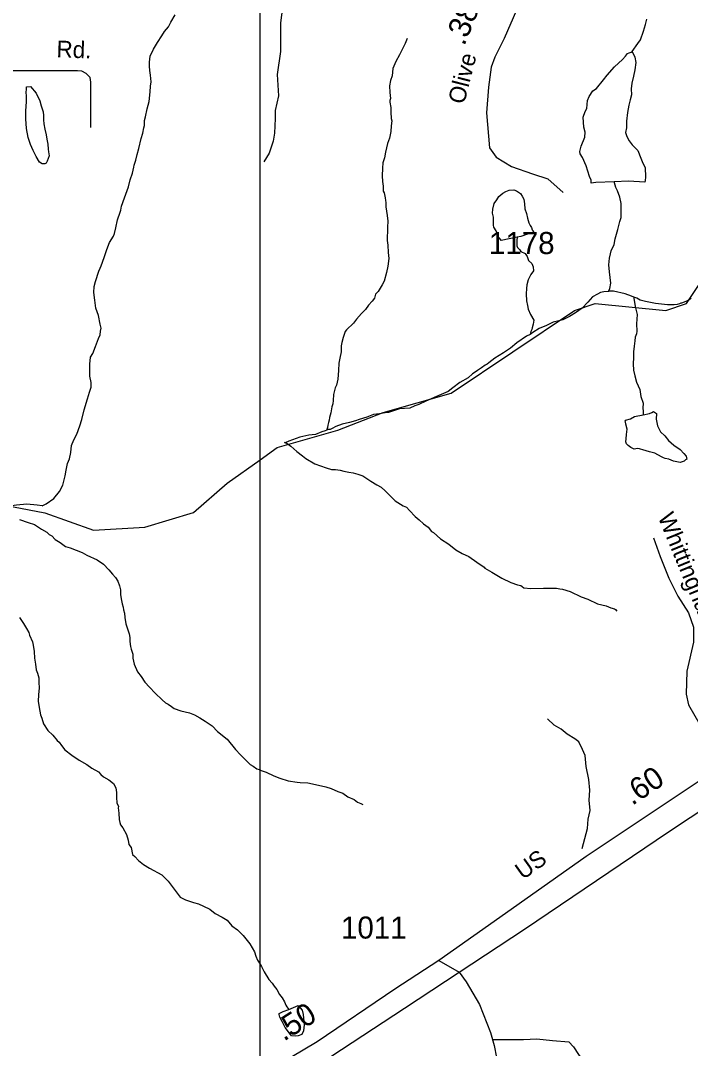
# Model space of a CAD drawing. Extents: x 2001466 to 2224147, y 644118 to 847247.
# Drawn here: x 2019117 to 2022908, y 703581 to 709402 of the extents above; entities that cross this region are included whole.
import ezdxf

# ---------------------------------------------------------------- set-up
doc = ezdxf.new("R2010")
doc.units = 0
for name, color, linetype in [('Exist Hydrographic Creek Single Shore', 7, 'Continuous'), ('Exist Hydrographic Misc Water Feature', 7, 'Continuous'), ('Exist Railroad Mainline', 7, 'Continuous'), ('Exist Road Non-System Type 51', 7, 'Continuous'), ('Exist Road Non-System Type 51 Label', 7, 'Continuous'), ('Exist Road Secondary Mileage Hundredths English Label', 7, 'Continuous'), ('Exist Road Secondary Type 41 Attributed', 7, 'Continuous'), ('Exist Road Secondary Type 51 Attributed', 7, 'Continuous'), ('Exist Road Secondary Type 51 Label', 7, 'Continuous'), ('Exist Road Secondary Type 51 Number Label', 7, 'Continuous'), ('Map Preparation Inset Cut Line', 7, 'Continuous')]:
    doc.layers.add(name, color=color, linetype=linetype)

msp = doc.modelspace()

# ---------------------------------------------------------------- linework, layer by layer
at = {"layer": 'Exist Hydrographic Creek Single Shore'}
for points in [[(2020472.9, 706915.1), (2020569.7, 706983.8), (2020911.7, 707081.9)], [(2015804.7, 705555.1), (2015821.7, 705613.9), (2015996.8, 705820.2), (2016171.7, 705895.4), (2016662.8, 706013.4), (2017037.7, 705972.9), (2017254.8, 705998.1), (2018020.7, 706222), (2018162.8, 706363.5), (2018770.8, 706630), (2018986.7, 706665), (2019253.7, 706613.6), (2019528.9, 706516.1), (2019820.8, 706533.1), (2020095.8, 706616.1), (2020286.7, 706782.9), (2020472.9, 706915.1)]]:
    msp.add_lwpolyline(points, dxfattribs=at)
at = {"layer": 'Exist Hydrographic Misc Water Feature'}
for points in [[(2019239.3, 706653.2), (2019261.3, 706665.2), (2019305.1, 706695.2), (2019337.1, 706735.3), (2019355.2, 706771.3), (2019369.1, 706823.2), (2019375.1, 706855.2), (2019383.1, 706893.3), (2019393.1, 706919.3), (2019401.1, 706955.2), (2019405, 706995.2), (2019418.9, 707027.3), (2019434.9, 707059.3), (2019453, 707107.2), (2019462.8, 707143.3), (2019477, 707197.3), (2019494.8, 707259.2), (2019506.7, 707297.3), (2019516.8, 707325.3), (2019516.8, 707351.3), (2019508.8, 707387.2), (2019508.8, 707417.3), (2019508.8, 707455.3), (2019512.7, 707495.3), (2019524.8, 707517.2), (2019540.7, 707555.3), (2019558.6, 707601.3), (2019566.6, 707621.3), (2019568.6, 707643.2), (2019572.7, 707659.2), (2019566.6, 707683.3), (2019558.6, 707731.3), (2019542.6, 707773.2), (2019536.6, 707819.2), (2019530.5, 707861.2), (2019532.3, 707895.2), (2019540.3, 707923.2), (2019560.4, 707983.2), (2019566.4, 707999.3), (2019572.5, 708013.2), (2019590.4, 708059.2), (2019604.3, 708105.2), (2019620.3, 708145.2), (2019642.2, 708181.3), (2019648.4, 708195.2), (2019656.4, 708227.2), (2019664.4, 708273.3), (2019680.2, 708317.3), (2019684.3, 708327.3), (2019688.2, 708351.2), (2019704.2, 708397.3), (2019728.2, 708459.3), (2019736.2, 708499.3), (2019750.1, 708537.3), (2019758.1, 708571.3), (2019760.2, 708583.3), (2019770, 708611.2), (2019776.1, 708643.3), (2019786, 708677.3), (2019799.9, 708733.3), (2019807.9, 708763.2), (2019813.9, 708793.3), (2019818, 708807.3), (2019818, 708835.3), (2019823.9, 708857.3), (2019833.8, 708901.2), (2019843.8, 708943.3), (2019849.8, 708997.3), (2019851.8, 709029.2), (2019855.9, 709055.3), (2019851.8, 709093.3), (2019847.7, 709119.3), (2019845.7, 709143.3), (2019845.7, 709165.2), (2019849.8, 709199.2), (2019869.6, 709239.3), (2019891.8, 709277.3), (2019915.6, 709315.3), (2019931.6, 709339.3), (2019953.5, 709365.3), (2019967.7, 709393.3), (2019991.7, 709433.4)], [(2022578.7, 709226.7), (2022611.4, 709271), (2022625.3, 709292.9), (2022643.2, 709340.9), (2022653.2, 709379), (2022661.2, 709409)], [(2021305.4, 709300.1), (2021293.5, 709272.1), (2021261.5, 709208.1), (2021241.7, 709170.1), (2021223.6, 709130.1), (2021219.5, 709088.1), (2021209.7, 709062.1), (2021205.6, 709032.1), (2021207.6, 708994.1), (2021209.7, 708960.1), (2021207.6, 708948.1), (2021207.6, 708940.1), (2021211.7, 708910.1), (2021211.7, 708882.1), (2021213.8, 708846.1), (2021217.7, 708834.2), (2021213.8, 708806.1), (2021211.7, 708774.1), (2021205.8, 708736.2), (2021193.9, 708706.2), (2021181.8, 708656.1), (2021175.8, 708624.1), (2021167.8, 708596.1), (2021166, 708566.1), (2021163.9, 708522.1), (2021166, 708490.2), (2021169.9, 708464.2), (2021169.9, 708436.2), (2021174, 708426.2), (2021175.8, 708416.1), (2021179.9, 708398.1), (2021182, 708382.2), (2021184, 708372.2), (2021184, 708362.2), (2021184, 708346.2), (2021192, 708298.2), (2021196.1, 708266.2), (2021194.1, 708232.2), (2021194.1, 708206.2), (2021192, 708176.2), (2021192.2, 708156.2), (2021196.1, 708130.1), (2021198.2, 708088.2), (2021202.1, 708054.2), (2021196.1, 708010.2), (2021188.1, 707974.2), (2021174.2, 707926.2), (2021164.3, 707904.2), (2021140.4, 707868.1), (2021126.2, 707852.2), (2021120.3, 707830.2), (2021106.3, 707812.2), (2021086.2, 707790.2), (2021068.4, 707766.2), (2021046.4, 707742.2), (2021018.3, 707710.1), (2021000.5, 707688.2), (2020962.4, 707650.1), (2020954.4, 707640.2), (2020942.5, 707606.1), (2020934.5, 707578.1), (2020930.6, 707560.1), (2020930.6, 707526.1), (2020924.4, 707490.1), (2020918.5, 707462.1), (2020916.4, 707420.1), (2020912.7, 707370.2), (2020904.8, 707336.2), (2020896.5, 707322.1), (2020888.6, 707284.2), (2020886.7, 707250.2), (2020884.7, 707232.2), (2020878.7, 707214.1), (2020872.6, 707180.1), (2020864.8, 707154.1), (2020862.7, 707138.1), (2020858.8, 707126.2), (2020856.8, 707110.1), (2020854.7, 707098.1), (2020850.8, 707086.2), (2020850.8, 707082.2)], [(2022475.9, 708488.9), (2022373.7, 708484.9), (2022345.9, 708480.9), (2022345.9, 708496.9), (2022337.9, 708518.9), (2022317.8, 708578.9), (2022297.7, 708626.8), (2022283.7, 708646.8), (2022281.7, 708660.8), (2022289.7, 708690.8), (2022309.8, 708740.8), (2022311.6, 708768.8), (2022305.5, 708798.8), (2022301.6, 708854.8), (2022311.6, 708886.8), (2022321.7, 708902.7), (2022325.6, 708948.8), (2022335.6, 708970.8), (2022355.5, 709002.8), (2022377.4, 709016.8), (2022415.4, 709066.8), (2022437.5, 709092.9), (2022479.3, 709138.9), (2022501.3, 709160.9), (2022523.2, 709180.9), (2022541.3, 709200.9), (2022551.3, 709214.9), (2022561.4, 709218.9), (2022573.3, 709222.9), (2022578.7, 709226.7)], [(2022578.7, 709226.7), (2022593.4, 709194.9), (2022599.3, 709164.9), (2022593.4, 709123), (2022585.4, 709086.9), (2022577.4, 709046.9), (2022573.5, 709014.9), (2022575.5, 708981), (2022567.5, 708952.9), (2022559.5, 708922.9), (2022551.5, 708880.9), (2022545.6, 708831), (2022545.6, 708794.9), (2022541.5, 708766.9), (2022547.6, 708744.9), (2022561.8, 708721), (2022577.8, 708697), (2022609.8, 708665), (2022627.6, 708623), (2022639.7, 708595), (2022651.6, 708569), (2022653.6, 708515.1), (2022651.6, 708495), (2022649.7, 708487.1), (2022557.9, 708493), (2022475.9, 708488.9)], [(2019253.9, 708786.9), (2019262.1, 708754.9), (2019266.2, 708730.9), (2019270.1, 708701), (2019272.1, 708673), (2019274.2, 708659), (2019278.1, 708635), (2019268, 708604.9), (2019262.1, 708595), (2019254.3, 708590.9), (2019238.1, 708590.9), (2019224.1, 708598.9), (2019204, 708630.9), (2019188.1, 708664.9), (2019172.1, 708698.9), (2019160.2, 708738.9), (2019150.1, 708790.9), (2019146, 708844.9), (2019146, 708890.9), (2019149.9, 708940.9), (2019149.9, 708970.9), (2019147.9, 708998.8), (2019149.9, 709008.8), (2019149.9, 709026.8), (2019172.1, 709028.8), (2019204, 708990.9), (2019226, 708946.9), (2019234, 708918.9), (2019244, 708884.9), (2019245.9, 708864.9), (2019245.9, 708839), (2019247.9, 708817), (2019253.9, 708786.9)], [(2022444.1, 707867), (2022452.1, 707885), (2022458, 707915), (2022450, 707979), (2022446.1, 708019), (2022450, 708057), (2022456, 708081), (2022459.9, 708097), (2022475.9, 708133), (2022482, 708165), (2022498, 708219), (2022507.8, 708263), (2022515.8, 708287), (2022515.8, 708319), (2022515.8, 708365), (2022507.8, 708401), (2022495.7, 708437), (2022485.7, 708456.9), (2022477.7, 708482.9), (2022475.9, 708488.9)], [(2021928, 708174.6), (2021837.9, 708156.6), (2021829.9, 708166.6), (2021820.1, 708176.5), (2021818.1, 708190.5), (2021808, 708210.5), (2021796.1, 708232.6), (2021794.1, 708242.6), (2021793.9, 708270.6), (2021793.9, 708288.5), (2021787.9, 708310.5), (2021790, 708334.5), (2021798, 708366.6), (2021811.9, 708386.6), (2021824, 708404.6), (2021845.9, 708424.5), (2021864, 708434.5), (2021881.8, 708440.6), (2021907.9, 708442.6), (2021923.9, 708436.6), (2021946, 708422.6), (2021955.8, 708406.6), (2021965.9, 708390.7), (2021970, 708364.7), (2021971.8, 708334.7), (2021979.8, 708308.7), (2021986, 708282.7), (2021994, 708256.7), (2022002, 708240.7), (2022007.9, 708230.7), (2022012, 708216.7), (2022022.1, 708206.7), (2022018, 708202.7), (2021948.1, 708178.7), (2021928, 708174.6)], [(2021928, 708174.6), (2021926.1, 708158.6), (2021926.1, 708126.7), (2021930, 708116.7), (2021942.1, 708102.7), (2021948.1, 708094.7), (2021972, 708082.7), (2021983.9, 708064.7), (2021991.9, 708042.7), (2022010, 708026.7), (2022018.2, 708006.8), (2022020.2, 707984.8), (2022004.2, 707962.7), (2021990.1, 707932.7), (2021982.1, 707904.7), (2021980.2, 707884.7), (2021978.2, 707854.8), (2021980.2, 707814.7), (2021986.2, 707788.7), (2021990.3, 707766.7), (2022002.2, 707736.8), (2022022.3, 707704.8), (2022018.2, 707682.8), (2022012.2, 707660.7), (2022010.2, 707652.7), (2022004.2, 707640.7), (2022002.2, 707632.7), (2022000.3, 707624.7)], [(2020911.7, 707081.9), (2021169.7, 707181.6), (2021553.7, 707291.9), (2022252.8, 707760), (2022369.8, 707800.3), (2022769.7, 707759.3), (2022885.8, 707799.5), (2023002.8, 707974.4)], [(2022444.1, 707867), (2022418.2, 707865), (2022400.2, 707861), (2022382.2, 707853), (2022354.1, 707836.9), (2022328.2, 707806.9), (2022296.2, 707772.9), (2022258.1, 707746.9), (2022224.1, 707724.9), (2022202.1, 707714.9), (2022186.3, 707706.9), (2022164.2, 707700.9), (2022132.2, 707692.8), (2022094.3, 707674.8), (2022052.2, 707658.8), (2022016.3, 707634.8), (2022000.3, 707624.7)], [(2022588.2, 707835.1), (2022574.1, 707841.1), (2022538.2, 707855.1), (2022472.2, 707869), (2022452.1, 707869), (2022444.1, 707867)], [(2022588.2, 707835.1), (2022588.2, 707829.1), (2022596.2, 707783), (2022606.1, 707737.1), (2022602.2, 707685.1), (2022604.2, 707643.1), (2022602.2, 707627.1), (2022596.2, 707609.1), (2022594.2, 707587.1), (2022590.3, 707557.1), (2022586.2, 707525.1), (2022586.2, 707493.2), (2022584.3, 707457.1), (2022586.4, 707421.1), (2022594.4, 707389.2), (2022602.4, 707353.2), (2022622.5, 707313.2), (2022628.4, 707273.2), (2022640.5, 707235.2), (2022638.5, 707207.2), (2022640.5, 707189.2), (2022640.5, 707177.2), (2022640.5, 707169.2)], [(2022912, 707827.2), (2022892.1, 707815.2), (2022858.1, 707801.2), (2022854, 707801.2), (2022846.2, 707797.2), (2022834.1, 707793.2), (2022816, 707791.2), (2022798.2, 707791.2), (2022778.1, 707791.2), (2022744.1, 707795.2), (2022710.2, 707799.2), (2022654.1, 707811.1), (2022624.1, 707819.1), (2022604.2, 707829.1), (2022588.2, 707835.1)], [(2022000.3, 707624.7), (2021980.2, 707614.7), (2021926.3, 707576.8), (2021890.4, 707546.7), (2021850.5, 707520.7), (2021800.4, 707490.6), (2021766.4, 707462.6), (2021758.4, 707456.6), (2021746.5, 707450.6), (2021726.4, 707434.6), (2021702.6, 707420.6), (2021690.3, 707410.6), (2021674.5, 707400.6), (2021650.5, 707378.6), (2021602.5, 707352.5), (2021562.6, 707322.5), (2021536.5, 707300.6), (2021470.5, 707272.5), (2021410.6, 707246.5), (2021370.6, 707228.4), (2021348.7, 707220.4), (2021320.6, 707206.4), (2021290.7, 707204.3), (2021260.7, 707202.3), (2021210.7, 707186.3), (2021198.6, 707182.3), (2021192.6, 707182.3), (2021168.7, 707178.3), (2021148.6, 707174.3), (2021114.7, 707170.3), (2021076.6, 707156.3), (2021032.7, 707142.2), (2021012.8, 707134.2), (2020978.8, 707126.2), (2020936.7, 707116.2), (2020900.9, 707102.2), (2020880.8, 707092.2), (2020868.9, 707086.1), (2020856.8, 707086.2), (2020850.8, 707082.2)], [(2022640.5, 707169.2), (2022676.6, 707177.3), (2022690.5, 707181.3), (2022698.5, 707187.3), (2022716.6, 707177.3), (2022714.5, 707145.2), (2022722.5, 707107.2), (2022738.5, 707073.3), (2022762.5, 707049.3), (2022784.5, 707023.3), (2022814.4, 706997.3), (2022850.5, 706973.4), (2022870.6, 706949.4), (2022884.5, 706935.4), (2022886.6, 706925.4), (2022888.6, 706917.4), (2022880.6, 706913.4), (2022872.6, 706907.4), (2022850.7, 706899.4), (2022812.6, 706907.4), (2022786.7, 706917.3), (2022764.6, 706921.3), (2022756.6, 706925.3), (2022744.7, 706931.3), (2022706.5, 706951.3), (2022676.6, 706959.2), (2022638.7, 706971.2), (2022626.6, 706975.2), (2022620.6, 706977.2), (2022608.5, 706979.2), (2022590.7, 706975.2), (2022582.7, 706979.2), (2022570.6, 706983.2), (2022556.7, 706995.2), (2022546.6, 707005.2), (2022542.7, 707015.2), (2022544.6, 707033.2), (2022546.6, 707057.2), (2022548.4, 707073.2), (2022550.5, 707087.2), (2022542.5, 707115.2), (2022540.5, 707129.1), (2022538.6, 707133.2), (2022540.5, 707139.2), (2022568.5, 707147.2), (2022592.5, 707159.2), (2022640.5, 707169.2)], [(2020850.8, 707082.2), (2020840.8, 707078.2), (2020822.7, 707072.1), (2020786.8, 707058.1), (2020748.7, 707054.1), (2020696.8, 707042), (2020656.8, 707028), (2020634.9, 707020), (2020617.8, 707012.7), (2020614.2, 707011.2), (2020610.9, 707011.9)], [(2020610.9, 707011.9), (2020614.2, 707011.2), (2020617.8, 707012.7), (2020646.8, 706992), (2020680.8, 706962), (2020712.8, 706936.1), (2020730.9, 706922.1), (2020782.9, 706892.1), (2020846.9, 706868.2), (2020876.9, 706860.2), (2020898.8, 706860.2), (2020924.8, 706856.2), (2020946.8, 706850.2), (2020974.9, 706844.2), (2020998.9, 706840.2), (2021024.9, 706832.3), (2021054.8, 706824.3), (2021098.9, 706794.3), (2021133, 706772.3), (2021157, 706760.3), (2021181, 706738.4), (2021236.9, 706682.4), (2021282.9, 706654.5), (2021300.9, 706646.5), (2021319, 706626.5), (2021350.9, 706592.5), (2021373.1, 706574.5), (2021397.1, 706552.5), (2021422.9, 706532.5), (2021443, 706508.5), (2021454.9, 706502.6), (2021493, 706466.6), (2021541, 706436.6), (2021581, 706404.7), (2021616.9, 706384.7), (2021653.2, 706366.7), (2021699.1, 706334.7), (2021741.2, 706306.8), (2021745.1, 706300.7), (2021785, 706278.8), (2021841, 706244.8), (2021891.1, 706218.9), (2021929.2, 706206.9), (2021949.1, 706202.9), (2021955, 706196.9), (2021965.1, 706188.9), (2022005.1, 706185), (2022077, 706187), (2022115.2, 706187), (2022151.1, 706187.1), (2022169.1, 706183.1), (2022185.1, 706181.1), (2022227.1, 706169.1), (2022289.1, 706139.1), (2022327.2, 706125.2), (2022383.2, 706099.2), (2022431.2, 706087.3), (2022457.2, 706075.3), (2022479.1, 706071.3), (2022485.1, 706067.3), (2022491, 706057.2)], [(2019239.3, 706653.2), (2019211.2, 706657.2), (2019151.4, 706663.1), (2019093.3, 706657.1), (2019055.2, 706651.1), (2019039.2, 706651.1)], [(2019111.4, 706577.1), (2019159.3, 706559.1), (2019195.2, 706547.2), (2019235.2, 706521.2), (2019265.4, 706505.3), (2019279.3, 706491.3), (2019293.2, 706483.3), (2019313.3, 706463.3), (2019341.4, 706445.3), (2019371.4, 706423.3), (2019397.4, 706415.3), (2019431.5, 706403.3), (2019465.3, 706389.4), (2019491.3, 706373.4), (2019549.4, 706347.4), (2019585.4, 706323.4), (2019615.4, 706291.4), (2019637.3, 706267.5), (2019653.3, 706247.5), (2019667.5, 706227.5), (2019677.3, 706201.5), (2019681.4, 706177.5), (2019681.4, 706149.5), (2019687.6, 706117.6), (2019691.5, 706099.6), (2019697.4, 706079.6), (2019699.5, 706065.6), (2019705.4, 706045.6), (2019707.5, 706021.6), (2019713.4, 705985.6), (2019721.6, 705957.6), (2019731.6, 705929.6), (2019735.5, 705907.6), (2019735.5, 705885.6), (2019739.6, 705857.7), (2019743.5, 705841.6), (2019751.5, 705813.6), (2019751.5, 705791.6), (2019759.5, 705757.6), (2019777.8, 705713.7), (2019799.7, 705687.7), (2019819.8, 705655.6), (2019845.7, 705627.7), (2019877.6, 705593.7), (2019917.6, 705555.8), (2019937.7, 705537.8), (2019951.7, 705529.8), (2019971.8, 705517.8), (2019985.7, 705505.8), (2020023.8, 705493.8), (2020073.7, 705481.8), (2020101.8, 705469.9), (2020131.7, 705453.9), (2020161.8, 705433.9), (2020201.8, 705408), (2020231.8, 705375.9), (2020285.9, 705332), (2020333.9, 705274), (2020361.8, 705244.1), (2020391.9, 705214.1), (2020415.9, 705188.1), (2020433.7, 705180.1), (2020454, 705164.2), (2020468, 705160.2), (2020478, 705154.1), (2020505.9, 705146.1), (2020550, 705124.2), (2020584, 705112.2), (2020632, 705096.2), (2020681.9, 705088.3), (2020699.9, 705086.2), (2020741.9, 705084.4), (2020803.9, 705072.4), (2020844.1, 705062.4), (2020874, 705052.4), (2020911.9, 705036.4), (2020940, 705026.5), (2020970, 705006.5), (2021004, 704990.5), (2021023.9, 704976.5), (2021041.9, 704968.5), (2021054, 704962.6)], [(2019109.7, 706021.2), (2019133.7, 705987.2), (2019149.7, 705959.3), (2019163.7, 705937.3), (2019167.5, 705921.3), (2019183.7, 705883.2), (2019187.6, 705865.2), (2019193.8, 705829.3), (2019195.6, 705791.3), (2019201.8, 705757.3), (2019205.7, 705725.3), (2019211.8, 705705.3), (2019219.8, 705679.3), (2019219.8, 705653.3), (2019221.9, 705623.3), (2019217.8, 705583.3), (2019215.9, 705547.3), (2019221.9, 705511.3), (2019229.9, 705469.3), (2019237.9, 705451.4), (2019246.1, 705419.4), (2019271.9, 705381.4), (2019300, 705355.4), (2019324, 705325.4), (2019335.9, 705315.4), (2019348, 705297.5), (2019367.9, 705271.5), (2019406, 705241.5), (2019448.1, 705213.5), (2019491.9, 705189.5), (2019520, 705167.6), (2019558.2, 705147.6), (2019570.1, 705131.6), (2019586.1, 705119.6), (2019616, 705101.6), (2019642, 705081.6), (2019656.2, 705057.6), (2019660.1, 705029.7), (2019660.1, 705001.6), (2019662.1, 704971.7), (2019670.1, 704951.7), (2019668.3, 704943.7), (2019672.2, 704913.7), (2019674.2, 704877.7), (2019678.1, 704859.7), (2019682.2, 704847.7), (2019696.2, 704829.7), (2019716.3, 704791.7), (2019726.1, 704759.8), (2019730.2, 704735.8), (2019742.3, 704719.8), (2019750.3, 704679.7), (2019764.3, 704667.7), (2019784.3, 704645.7), (2019812.2, 704621.8), (2019846.3, 704601.8), (2019916.4, 704563.9), (2019952.3, 704527.9), (2019980.4, 704490), (2020002.3, 704460), (2020020.4, 704437.9), (2020050.5, 704421.9), (2020096.4, 704408), (2020124.5, 704400), (2020152.4, 704386), (2020188.5, 704370.1), (2020218.4, 704346.1), (2020258.4, 704324.1), (2020286.5, 704308.1), (2020312.4, 704276.1), (2020344.3, 704252.2), (2020376.5, 704220.2), (2020414.5, 704174.3)], [(2020414.5, 704174.3), (2020440.5, 704128.2), (2020448.5, 704104.3), (2020458.6, 704080.3), (2020468.6, 704064.3), (2020480.5, 704044.3), (2020494.6, 704014.3), (2020522.5, 703972.4), (2020540.6, 703950.3), (2020552.5, 703934.3), (2020566.6, 703914.4), (2020582.6, 703886.4), (2020596.8, 703868.4), (2020610.7, 703844.4), (2020618.7, 703826.4), (2020624.6, 703816.4), (2020634.7, 703802.4)], [(2020634.7, 703802.4), (2020688.6, 703824.5), (2020710.8, 703798.5), (2020716.7, 703772.5), (2020720.6, 703734.4), (2020722.7, 703714.5), (2020718.8, 703680.5), (2020708.7, 703660.5), (2020688.6, 703652.5), (2020670.8, 703650.5), (2020650.9, 703652.5), (2020644.7, 703660.5), (2020614.8, 703700.4), (2020596.8, 703734.4), (2020584.7, 703758.4), (2020580.8, 703772.4), (2020580.8, 703778.4), (2020602.7, 703790.4), (2020634.7, 703802.4)]]:
    msp.add_lwpolyline(points, dxfattribs=at)
at = {"layer": 'Exist Railroad Mainline'}
for points in [[(2021599.5, 704013.4), (2021968.5, 704257.4), (2022784.4, 704808.2), (2023632.3, 705367.4), (2024128.2, 705691.9)], [(2019262.5, 702465.7), (2019299.1, 702489.6), (2019971.3, 702930.1), (2020472.9, 703269.2), (2020637.8, 703380.6), (2021290.1, 703808.9), (2021599.5, 704013.4)]]:
    msp.add_lwpolyline(points, dxfattribs=at)
at = {"layer": 'Exist Road Non-System Type 51'}
for points in [[(2020621.8, 710131.7), (2020621.8, 709841.3), (2020614.2, 709683.1), (2020606.7, 709536.2), (2020587.9, 709389.2), (2020587.9, 709227.3), (2020569.1, 709095.4), (2020576.6, 708974.9), (2020557.8, 708892), (2020557.8, 708846.8), (2020554, 708763.9), (2020546.5, 708718.7), (2020535.2, 708684.8), (2020523.9, 708650.9), (2020493.8, 708601.9)], [(2019514.6, 708796.9), (2019514.6, 709053.1), (2019510.4, 709080), (2019487.7, 709102.7), (2019462.9, 709115.1), (2019438.2, 709117.2), (2019039.7, 709117.2), (2018855.9, 709111), (2018829.1, 709102.7), (2018758.9, 709084.1), (2018686.6, 709077.9), (2018261.3, 709084.1), (2017914.2, 709088.3)], [(2022698.6, 706471.6), (2022736.5, 706367.4), (2022787, 706244.2), (2022837.5, 706143.1), (2022897.5, 706048.3), (2022925.9, 705966.2), (2022925.9, 705880.9), (2022888.1, 705716.7), (2022884.9, 705587.1), (2022897.5, 705527.1), (2022989.1, 705366), (2023109.8, 705196.4)], [(2022296.1, 704713.1), (2022325.6, 704826.4), (2022329.7, 704880.3), (2022341.7, 704928.2), (2022335.8, 704986.4), (2022338, 705044.3), (2022334.1, 705104.2), (2022318.2, 705178.3), (2022312.4, 705240.3), (2022296.5, 705274.4), (2022276.6, 705316.4), (2022254.5, 705334.4), (2022210.7, 705360.5), (2022176.6, 705388.6), (2022136.7, 705412.6), (2022098.8, 705446.8)], [(2021788.3, 703630.9), (2021904.1, 703630.9), (2021964, 703630.9), (2022039.8, 703634.8), (2022127.6, 703626.9), (2022219.4, 703618.9), (2022247.3, 703590.9), (2022275.3, 703547), (2022339.1, 703459.1), (2022387, 703395.2), (2022528.6, 703315.3)]]:
    msp.add_lwpolyline(points, dxfattribs=at)
at = {"layer": 'Exist Road Secondary Type 41 Attributed'}
msp.add_lwpolyline([(2022029.6, 710203.3), (2022027.2, 709999.7), (2022001.7, 709713.9), (2021985.3, 709629.3), (2021923.1, 709460.9), (2021853.3, 709299.6), (2021801.5, 709194.2), (2021780.7, 709136.8), (2021764.8, 709025), (2021753.6, 708879.7), (2021771.5, 708681.7), (2021808.2, 708627.5), (2021895.6, 708575.6), (2022014.4, 708534.1), (2022101.4, 708506.1), (2022187.2, 708427.9)], dxfattribs=at)
at = {"layer": 'Exist Road Secondary Type 51 Attributed'}
for points in [[(2024071.2, 705851.1), (2023713.8, 705605.2), (2023234.4, 705279.5), (2022577.9, 704842), (2022317.8, 704668), (2021765, 704276.9), (2021484.2, 704078.9)], [(2021484.2, 704078.9), (2021234.5, 703917.6), (2020795.8, 703619.1), (2020496.6, 703441.9), (2020134.5, 703259.9), (2019623.1, 703026.8), (2019326.4, 702876.7), (2019122.1, 702770.6)], [(2021484.2, 704078.9), (2021599.5, 704013.4)], [(2021599.5, 704013.4), (2021639.8, 703959.2), (2021714.7, 703829.8), (2021777, 703671.8), (2021797.3, 703598.3), (2021810.1, 703530.5), (2021802.1, 703434.7), (2021763.8, 703195.2), (2021747.4, 703046.7), (2021748.2, 702759.4), (2021759.4, 702534.2), (2021774.2, 702301.1), (2021790.9, 702125.5), (2021821.2, 702024.9), (2021938.9, 701743.2), (2022009.1, 701633.8), (2022088.9, 701541.2), (2022176.6, 701477.3), (2022288.3, 701426.2), (2022433.5, 701373.6), (2022475.3, 701360.4)]]:
    msp.add_lwpolyline(points, dxfattribs=at)
at = {"layer": 'Map Preparation Inset Cut Line'}
for p, q in [((2020472.9, 706915.1), (2020472.9, 710121.8)), ((2020472.9, 703473), (2020472.9, 706915.1))]:
    msp.add_line(p, q, dxfattribs=at)

# ---------------------------------------------------------------- texts
at = {"layer": 'Exist Road Non-System Type 51 Label'}
for s, rotation, p in [('Rd.', 358.04193, (2019318.7, 709193.7)), ('Whittingham', 292.37493, (2022722.4, 706591.9))]:
    msp.add_text(s, height=95, rotation=rotation, dxfattribs=at).set_placement(p)
at = {"layer": 'Exist Road Secondary Mileage Hundredths English Label'}
for s, rotation, p in [('.38', 68.03973, (2021628.2, 709253.7)), ('.60', 33.903, (2022578.3, 704953.7)), ('.50', 32.48988, (2020607, 703618.7))]:
    msp.add_text(s, height=125, rotation=rotation, dxfattribs=at).set_placement(p)
at = {"layer": 'Exist Road Secondary Type 51 Label'}
for s, rotation, p in [('Olive', 75.67108, (2021627, 708923.3)), ('US', 35.52636, (2021959.8, 704533.5))]:
    msp.add_text(s, height=95, rotation=rotation, dxfattribs=at).set_placement(p)
at = {"layer": 'Exist Road Secondary Type 51 Number Label'}
for s, p in [('1178', (2021767.6, 708079.3)), ('1011', (2020930.1, 704203.2))]:
    msp.add_text(s, height=125, dxfattribs=at).set_placement(p)

doc.saveas('drawing.dxf')
